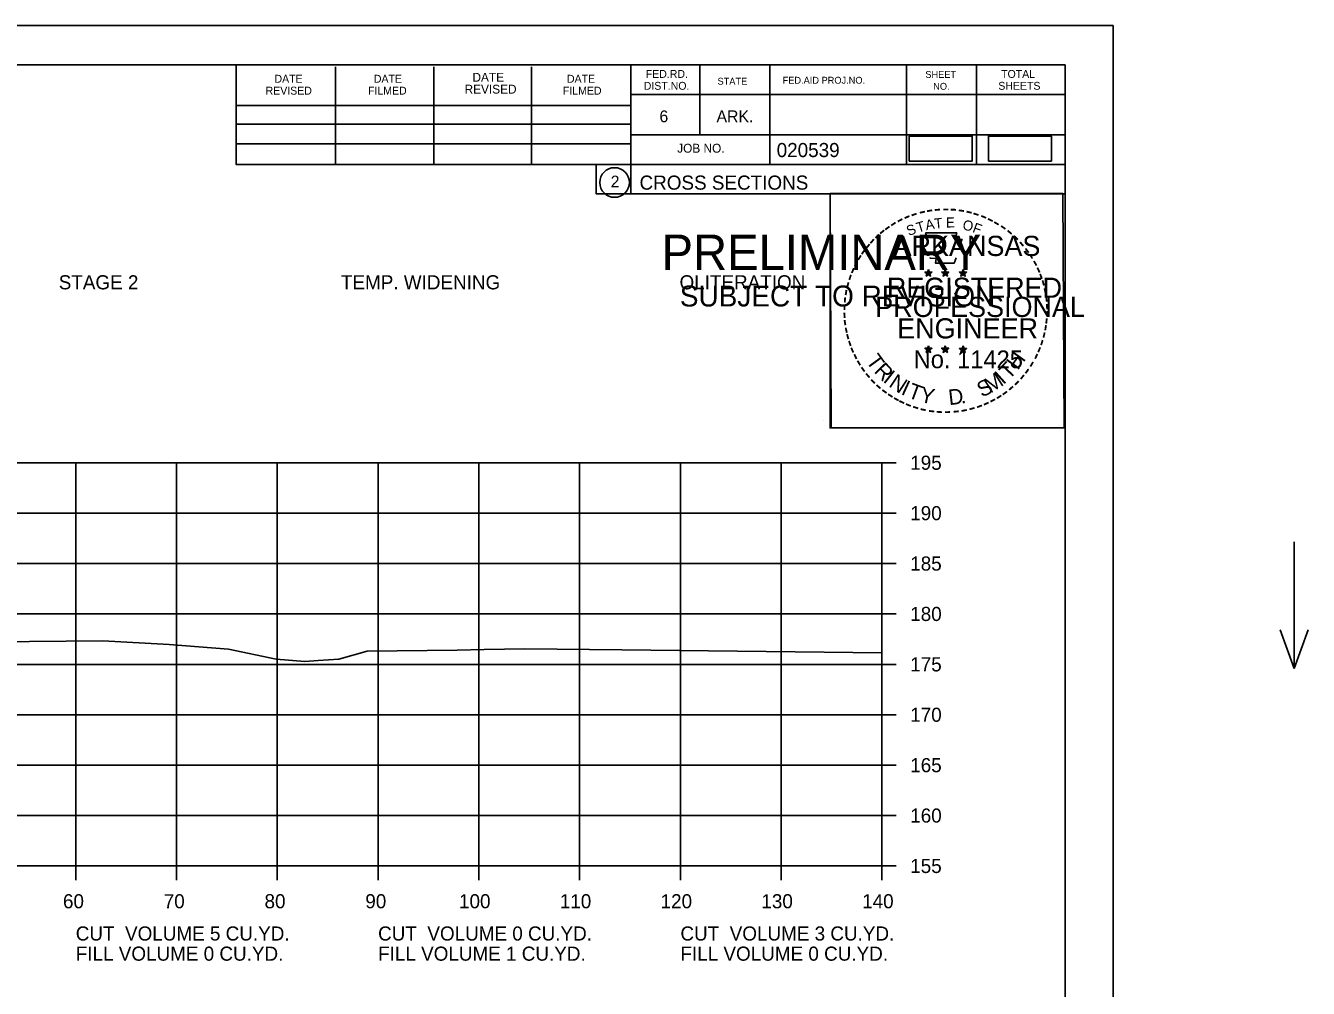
# Model space of a CAD drawing. Extents: x 915787 to 919910, y 133456 to 136717.
# Drawn here: x 916469 to 916596.3, y 133573.9 to 133669.4 of the extents above; entities that cross this region are included whole.
import ezdxf

# ---------------------------------------------------------------- set-up
doc = ezdxf.new("R2010")
doc.units = 0
for name, color, linetype in [('R_Axis', 7, 'Continuous'), ('R_Axis Annot', 7, 'Continuous'), ('R_Border', 7, 'Continuous'), ('R_Border Notes', 7, 'Continuous'), ('R_Border PE', 7, 'Continuous'), ('R_Border Prem', 7, 'Continuous'), ('R_Exist Surface', 7, 'Continuous'), ('R_Grid', 7, 'Continuous'), ('R_No Plot', 7, 'Continuous'), ('R_Water Annot', 7, 'Continuous'), ('R_Xsect Slope', 7, 'Continuous')]:
    doc.layers.add(name, color=color, linetype=linetype)

msp = doc.modelspace()

# ---------------------------------------------------------------- linework, layer by layer
at = {"layer": 'R_Axis'}
for p, q in [((916553.98, 133586.01), (916553.98, 133626.01)), ((916555.38, 133626.01), (916553.98, 133626.01)), ((916555.38, 133621.01), (916553.98, 133621.01)), ((916555.38, 133616.01), (916553.98, 133616.01)), ((916555.38, 133611.01), (916553.98, 133611.01)), ((916555.38, 133606.01), (916553.98, 133606.01)), ((916555.38, 133601.01), (916553.98, 133601.01)), ((916555.38, 133596.01), (916553.98, 133596.01)), ((916555.38, 133591.01), (916553.98, 133591.01)), ((916273.98, 133586.01), (916553.98, 133586.01)), ((916473.98, 133584.61), (916473.98, 133586.01)), ((916483.98, 133584.61), (916483.98, 133586.01)), ((916493.98, 133584.61), (916493.98, 133586.01)), ((916503.98, 133584.61), (916503.98, 133586.01)), ((916513.98, 133584.61), (916513.98, 133586.01)), ((916523.98, 133584.61), (916523.98, 133586.01)), ((916533.98, 133584.61), (916533.98, 133586.01)), ((916543.98, 133584.61), (916543.98, 133586.01)), ((916553.98, 133584.61), (916553.98, 133586.01)), ((916555.38, 133586.01), (916553.98, 133586.01))]:
    msp.add_line(p, q, dxfattribs=at)
at = {"layer": 'R_Border'}
for p, q in [((916255.98, 133665.47), (916572.16, 133665.47)), ((916489.9, 133655.59), (916489.9, 133665.47)), ((916499.76, 133655.59), (916499.76, 133665.27)), ((916509.52, 133655.59), (916509.52, 133665.27)), ((916519.2, 133655.59), (916519.2, 133665.27)), ((916529.06, 133665.47), (916529.06, 133652.67)), ((916535.9, 133665.47), (916535.9, 133658.53)), ((916542.84, 133665.47), (916542.84, 133655.59)), ((916556.42, 133665.47), (916556.42, 133655.59)), ((916563.36, 133665.47), (916563.36, 133655.59)), ((916572.16, 133460.01), (916572.16, 133665.47)), ((916489.9, 133661.45), (916529.06, 133661.45)), ((916572.16, 133662.53), (916529.06, 133662.53)), ((916572.16, 133662.55), (916572.16, 133662.55)), ((916489.9, 133659.59), (916529.06, 133659.59)), ((916489.9, 133655.59), (916489.9, 133657.65)), ((916489.9, 133657.65), (916529.06, 133657.65)), ((916572.16, 133658.53), (916529.06, 133658.53)), ((916532.02, 133658.53), (916572.16, 133658.53)), ((916572.16, 133655.59), (916489.9, 133655.59)), ((916529.06, 133652.67), (916572.16, 133652.67))]:
    msp.add_line(p, q, dxfattribs=at)
msp.add_circle((916527.44, 133653.81), 1.47, dxfattribs=at)
at = {"layer": 'R_Border PE'}
for p, q in [((916558.24, 133644.93), (916558.59, 133644.82)), ((916558.24, 133644.93), (916558.49, 133644.88)), ((916558.24, 133644.93), (916558.48, 133644.81)), ((916558.59, 133645.18), (916558.55, 133644.93)), ((916558.59, 133644.82), (916558.59, 133645.18)), ((916558.59, 133645.18), (916558.64, 133644.93)), ((916558.94, 133644.93), (916558.59, 133644.82)), ((916558.94, 133644.93), (916558.65, 133644.88)), ((916558.94, 133644.93), (916558.73, 133644.83)), ((916559.91, 133644.93), (916560.26, 133644.82)), ((916559.91, 133644.93), (916560.16, 133644.88)), ((916559.91, 133644.93), (916560.15, 133644.81)), ((916560.26, 133645.18), (916560.22, 133644.93)), ((916560.26, 133644.82), (916560.26, 133645.18)), ((916560.26, 133645.18), (916560.31, 133644.93)), ((916560.61, 133644.93), (916560.26, 133644.82)), ((916560.61, 133644.93), (916560.32, 133644.88)), ((916560.61, 133644.93), (916560.4, 133644.83)), ((916561.67, 133644.92), (916562.02, 133644.81)), ((916561.67, 133644.92), (916561.93, 133644.87)), ((916561.67, 133644.92), (916561.91, 133644.8)), ((916562.02, 133645.17), (916561.98, 133644.92)), ((916562.02, 133644.81), (916562.02, 133645.17)), ((916562.02, 133645.17), (916562.07, 133644.92)), ((916562.37, 133644.92), (916562.02, 133644.81)), ((916562.37, 133644.92), (916562.08, 133644.87)), ((916562.37, 133644.92), (916562.17, 133644.82)), ((916558.37, 133644.52), (916558.59, 133644.82)), ((916558.37, 133644.52), (916558.5, 133644.77)), ((916558.37, 133644.52), (916558.59, 133644.74)), ((916558.8, 133644.52), (916558.59, 133644.82)), ((916558.8, 133644.52), (916558.59, 133644.74)), ((916558.8, 133644.52), (916558.66, 133644.81)), ((916560.04, 133644.52), (916560.26, 133644.82)), ((916560.04, 133644.52), (916560.17, 133644.77)), ((916560.04, 133644.52), (916560.26, 133644.74)), ((916560.47, 133644.52), (916560.26, 133644.82)), ((916560.47, 133644.52), (916560.26, 133644.74)), ((916560.47, 133644.52), (916560.33, 133644.81)), ((916561.81, 133644.51), (916562.02, 133644.81)), ((916561.81, 133644.51), (916561.93, 133644.75)), ((916561.81, 133644.51), (916562.02, 133644.73)), ((916562.24, 133644.51), (916562.02, 133644.81)), ((916562.24, 133644.51), (916562.02, 133644.72)), ((916562.24, 133644.51), (916562.1, 133644.8)), ((916558.24, 133637.36), (916558.58, 133637.25)), ((916558.24, 133637.36), (916558.49, 133637.31)), ((916558.24, 133637.36), (916558.47, 133637.23)), ((916558.37, 133636.95), (916558.58, 133637.25)), ((916558.58, 133637.61), (916558.54, 133637.36)), ((916558.58, 133637.25), (916558.58, 133637.61)), ((916558.58, 133637.61), (916558.63, 133637.36)), ((916558.93, 133637.36), (916558.58, 133637.25)), ((916558.8, 133636.95), (916558.58, 133637.25)), ((916558.93, 133637.36), (916558.65, 133637.31)), ((916558.8, 133636.95), (916558.66, 133637.24)), ((916558.93, 133637.36), (916558.73, 133637.25)), ((916559.9, 133637.36), (916560.25, 133637.25)), ((916559.9, 133637.36), (916560.16, 133637.31)), ((916559.9, 133637.36), (916560.14, 133637.23)), ((916560.04, 133636.95), (916560.25, 133637.25)), ((916560.25, 133637.61), (916560.21, 133637.36)), ((916560.25, 133637.25), (916560.25, 133637.61)), ((916560.25, 133637.61), (916560.3, 133637.36)), ((916560.6, 133637.36), (916560.25, 133637.25)), ((916560.47, 133636.95), (916560.25, 133637.25)), ((916560.6, 133637.36), (916560.31, 133637.31)), ((916560.47, 133636.95), (916560.33, 133637.24)), ((916560.6, 133637.36), (916560.4, 133637.25)), ((916561.67, 133637.35), (916562.02, 133637.24)), ((916561.67, 133637.35), (916561.92, 133637.3)), ((916561.67, 133637.35), (916561.91, 133637.22)), ((916561.8, 133636.94), (916562.02, 133637.24)), ((916562.02, 133637.6), (916561.98, 133637.35)), ((916562.02, 133637.24), (916562.02, 133637.6)), ((916562.02, 133637.6), (916562.07, 133637.35)), ((916562.37, 133637.35), (916562.02, 133637.24)), ((916562.23, 133636.94), (916562.02, 133637.24)), ((916562.37, 133637.35), (916562.08, 133637.3)), ((916562.23, 133636.94), (916562.1, 133637.23)), ((916562.37, 133637.35), (916562.16, 133637.24)), ((916558.37, 133636.95), (916558.49, 133637.19)), ((916558.37, 133636.95), (916558.58, 133637.17)), ((916558.8, 133636.95), (916558.58, 133637.16)), ((916560.04, 133636.95), (916560.16, 133637.19)), ((916560.04, 133636.95), (916560.25, 133637.17)), ((916560.47, 133636.95), (916560.25, 133637.16)), ((916561.8, 133636.94), (916561.93, 133637.18)), ((916561.8, 133636.94), (916562.02, 133637.16)), ((916562.23, 133636.94), (916562.02, 133637.15))]:
    msp.add_line(p, q, dxfattribs=at)
for points in [[(916558.28, 133648.81), (916558.55, 133647.98)], [(916561.79, 133647.89), (916561.93, 133648.17), (916561.25, 133648.15), (916561.4, 133648.81), (916558.28, 133648.81)], [(916558.77, 133646.38), (916558.77, 133646.3), (916559.34, 133646.28), (916559.28, 133645.81), (916561.15, 133645.81), (916561.35, 133646.34)], [(916558.59, 133645.18), (916558.8, 133644.52), (916558.24, 133644.93), (916558.94, 133644.93), (916558.37, 133644.52), (916558.59, 133645.18)], [(916560.26, 133645.18), (916560.47, 133644.52), (916559.91, 133644.93), (916560.61, 133644.93), (916560.04, 133644.52), (916560.26, 133645.18)], [(916562.02, 133645.17), (916562.24, 133644.51), (916561.67, 133644.92), (916562.37, 133644.92), (916561.81, 133644.51), (916562.02, 133645.17)], [(916558.58, 133637.61), (916558.8, 133636.95), (916558.24, 133637.36), (916558.93, 133637.36), (916558.37, 133636.95), (916558.58, 133637.61)], [(916560.25, 133637.61), (916560.47, 133636.95), (916559.9, 133637.36), (916560.6, 133637.36), (916560.04, 133636.95), (916560.25, 133637.61)], [(916562.02, 133637.6), (916562.23, 133636.94), (916561.67, 133637.35), (916562.37, 133637.35), (916561.8, 133636.94), (916562.02, 133637.6)]]:
    msp.add_lwpolyline(points, dxfattribs=at)
for centre, radius in [((916558.59, 133644.82), 0.172), ((916558.59, 133644.82), 0.145), ((916558.59, 133644.82), 0.116), ((916558.59, 133644.82), 0.0991), ((916558.59, 133644.82), 0.0747), ((916558.59, 133644.82), 0.0495), ((916560.26, 133644.82), 0.172), ((916560.26, 133644.82), 0.145), ((916560.26, 133644.82), 0.116), ((916560.26, 133644.82), 0.0991), ((916560.26, 133644.82), 0.0747), ((916560.26, 133644.82), 0.0495), ((916562.02, 133644.81), 0.172), ((916562.02, 133644.81), 0.145), ((916562.02, 133644.81), 0.116), ((916562.02, 133644.81), 0.0991), ((916562.02, 133644.81), 0.0747), ((916562.02, 133644.81), 0.0495), ((916558.59, 133644.82), 0.0296), ((916560.26, 133644.82), 0.0296), ((916562.02, 133644.81), 0.0296), ((916558.58, 133637.25), 0.172), ((916558.58, 133637.25), 0.145), ((916558.58, 133637.25), 0.116), ((916558.58, 133637.25), 0.0991), ((916558.58, 133637.25), 0.0747), ((916558.58, 133637.25), 0.0495), ((916558.58, 133637.25), 0.0296), ((916560.25, 133637.25), 0.172), ((916560.25, 133637.25), 0.145), ((916560.25, 133637.25), 0.116), ((916560.25, 133637.25), 0.0991), ((916560.25, 133637.25), 0.0747), ((916560.25, 133637.25), 0.0495), ((916560.25, 133637.25), 0.0296), ((916562.02, 133637.24), 0.172), ((916562.02, 133637.24), 0.145), ((916562.02, 133637.24), 0.116), ((916562.02, 133637.24), 0.0991), ((916562.02, 133637.24), 0.0747), ((916562.02, 133637.24), 0.0495), ((916562.02, 133637.24), 0.0296)]:
    msp.add_circle(centre, radius, dxfattribs=at)
at = {"layer": 'R_Exist Surface'}
msp.add_lwpolyline([(916465.72, 133608.23), (916476.68, 133608.34), (916483.26, 133607.98), (916489.12, 133607.53), (916493.88, 133606.54), (916496.72, 133606.3), (916498.04, 133606.4), (916500.09, 133606.52), (916502.91, 133607.31), (916511.83, 133607.41), (916514.52, 133607.47), (916518.55, 133607.56), (916528.16, 133607.45), (916553.98, 133607.14)], dxfattribs=at)
at = {"layer": 'R_Grid'}
for p, q in [((916273.98, 133626.01), (916553.98, 133626.01)), ((916473.98, 133586.01), (916473.98, 133626.01)), ((916483.98, 133586.01), (916483.98, 133626.01)), ((916493.98, 133586.01), (916493.98, 133626.01)), ((916503.98, 133586.01), (916503.98, 133626.01)), ((916513.98, 133586.01), (916513.98, 133626.01)), ((916523.98, 133586.01), (916523.98, 133626.01)), ((916533.98, 133586.01), (916533.98, 133626.01)), ((916543.98, 133586.01), (916543.98, 133626.01)), ((916553.98, 133586.01), (916553.98, 133626.01)), ((916273.98, 133621.01), (916553.98, 133621.01)), ((916273.98, 133616.01), (916553.98, 133616.01)), ((916273.98, 133611.01), (916553.98, 133611.01)), ((916273.98, 133606.01), (916553.98, 133606.01)), ((916273.98, 133601.01), (916553.98, 133601.01)), ((916273.98, 133596.01), (916553.98, 133596.01)), ((916273.98, 133591.01), (916553.98, 133591.01)), ((916273.98, 133586.01), (916553.98, 133586.01))]:
    msp.add_line(p, q, dxfattribs=at)
at = {"layer": 'R_No Plot'}
for p, q in [((916243.57, 133669.37), (916576.91, 133669.37)), ((916548.19, 133630.22), (916548.19, 133630.22))]:
    msp.add_line(p, q, dxfattribs=at)
for points in [[(916243.57, 133669.37), (916576.91, 133669.37), (916576.91, 133456.03), (916243.57, 133456.03)], [(916489.9, 133665.47), (916489.9, 133655.59), (916525.63, 133655.59), (916525.63, 133652.67), (916548.83, 133652.67), (916548.83, 133629.46), (916572.16, 133629.46), (916572.16, 133460.01), (916255.98, 133460.01), (916255.98, 133665.47)], [(916548.83, 133652.71), (916571.92, 133652.71), (916572.04, 133629.46), (916548.94, 133629.46)]]:
    msp.add_lwpolyline(points, close=True, dxfattribs=at)
at = {"layer": 'R_Water Annot'}
for p, q in [((916594.88, 133618.16), (916594.88, 133605.59)), ((916594.88, 133605.59), (916593.48, 133609.44)), ((916594.88, 133605.59), (916596.28, 133609.44))]:
    msp.add_line(p, q, dxfattribs=at)
at = {"layer": 'R_Xsect Slope'}
for points in [[(916556.68, 133655.93), (916562.93, 133655.93), (916562.93, 133658.41), (916556.68, 133658.41)], [(916564.54, 133655.93), (916570.79, 133655.93), (916570.79, 133658.41), (916564.54, 133658.41)]]:
    msp.add_lwpolyline(points, close=True, dxfattribs=at)

# ---------------------------------------------------------------- texts
at = {"layer": 'R_Axis Annot'}
for s, p in [('195', (916556.78, 133625.31)), ('190', (916556.78, 133620.31)), ('185', (916556.78, 133615.31)), ('180', (916556.78, 133610.31)), ('175', (916556.78, 133605.31)), ('170', (916556.78, 133600.31)), ('165', (916556.78, 133595.31)), ('160', (916556.78, 133590.31)), ('155', (916556.78, 133585.31)), ('60', (916472.71, 133581.81)), ('70', (916482.71, 133581.81)), ('80', (916492.71, 133581.81)), ('90', (916502.71, 133581.81)), ('100', (916512.01, 133581.81)), ('110', (916522.01, 133581.81)), ('120', (916532.01, 133581.81)), ('130', (916542.01, 133581.81)), ('140', (916552.01, 133581.81))]:
    msp.add_text(s, height=1.4, dxfattribs=at).set_placement(p)
at = {"layer": 'R_Border'}
for s, height, p in [('DATE', 0.782, (916493.7, 133663.71)), ('DATE', 0.782, (916503.56, 133663.71)), ('DATE', 0.879, (916513.34, 133663.81)), ('DATE', 0.782, (916522.72, 133663.71)), ('FED.RD.', 0.782, (916530.54, 133664.19)), ('STATE', 0.684, (916537.66, 133663.51)), ('FED.AID PROJ.NO.', 0.684, (916544.12, 133663.61)), ('SHEET', 0.684, (916558.28, 133664.19)), ('TOTAL', 0.782, (916565.8, 133664.19)), ('REVISED', 0.782, (916492.82, 133662.53)), ('FILMED', 0.782, (916502.98, 133662.53)), ('REVISED', 0.879, (916512.56, 133662.63)), ('FILMED', 0.782, (916522.32, 133662.53)), ('DIST.NO.', 0.782, (916530.34, 133663.01)), ('NO.', 0.684, (916559.06, 133663.01)), ('SHEETS', 0.782, (916565.52, 133663.01)), ('6', 1.17, (916531.9, 133659.79)), ('ARK.', 1.172, (916537.56, 133659.79)), ('JOB NO.', 0.879, (916533.66, 133656.77)), ('020539', 1.4, (916543.53, 133656.33)), ('2', 1.17, (916527.06, 133653.32)), ('CROSS SECTIONS', 1.4, (916529.92, 133653.1))]:
    msp.add_text(s, height=height, rotation=360, dxfattribs=at).set_placement(p)
at = {"layer": 'R_Border Notes'}
for s, p in [('STAGE 2', (916472.29, 133643.21)), ('TEMP. WIDENING', (916500.29, 133643.21)), ('OLITERATION', (916533.89, 133643.21)), ('CUT  VOLUME 5 CU.YD.', (916473.98, 133578.61)), ('CUT  VOLUME 0 CU.YD.', (916503.98, 133578.61)), ('CUT  VOLUME 3 CU.YD.', (916533.98, 133578.61)), ('FILL VOLUME 0 CU.YD.', (916473.98, 133576.61)), ('FILL VOLUME 1 CU.YD.', (916503.98, 133576.61)), ('FILL VOLUME 0 CU.YD.', (916533.98, 133576.61))]:
    msp.add_text(s, height=1.4, dxfattribs=at).set_placement(p)
at = {"layer": 'R_Border PE'}
for s, height, rotation, p in [('-', 1.6, 0.1862, (916559.96, 133650.52)), ('-', 1.6, 28.7918, (916555.76, 133649.35)), ('-', 1.6, 24.3072, (916556.39, 133649.67)), ('-', 1.6, 19.1761, (916557.03, 133649.93)), ('T', 1, 16.4036, (916557.55, 133648.82)), ('-', 1.6, 13.6301, (916557.78, 133650.18)), ('A', 1, 11.2132, (916558.38, 133649.07)), ('-', 1.6, 10.2193, (916558.46, 133650.34)), ('T', 1, 6.0228, (916559.22, 133649.23)), ('-', 1.6, 5.8968, (916559.19, 133650.45)), ('E', 1, 0.8323, (916560.33, 133649.34)), ('-', 1.6, 357.743, (916560.68, 133650.51)), ('-', 1.6, 352.1617, (916561.42, 133650.45)), ('O', 1, 350.4515, (916561.93, 133649.13)), ('-', 1.6, 347.2049, (916562.14, 133650.34)), ('-', 1.6, 342.3362, (916562.78, 133650.18)), ('-', 1.6, 337.8551, (916563.51, 133649.96)), ('-', 1.6, 334.1211, (916564.14, 133649.69)), ('-', 1.6, 329.6409, (916564.72, 133649.4)), ('-', 1.6, 42.9622, (916553.68, 133647.79)), ('-', 1.6, 38.9507, (916554.11, 133648.21)), ('-', 1.6, 36.2317, (916554.59, 133648.58)), ('-', 1.6, 34.0636, (916555.16, 133648.98)), ('S', 1, 21.594, (916556.64, 133648.49)), ('F', 1, 340.0707, (916562.89, 133648.91)), ('-', 1.6, 325.8627, (916565.37, 133649.04)), ('-', 1.6, 320.5297, (916565.98, 133648.62)), ('-', 1.6, 50.6142, (916552.83, 133646.82)), ('-', 1.6, 48.423, (916553.23, 133647.31)), ('ARKANSAS', 2, 360, (916555.13, 133646.52)), ('-', 1.6, 315.5786, (916566.58, 133648.13)), ('-', 1.6, 309.8797, (916567.14, 133647.58)), ('-', 1.6, 58.0706, (916552.09, 133645.73)), ('-', 1.6, 54.2325, (916552.41, 133646.26)), ('-', 1.6, 306.6522, (916567.67, 133646.98)), ('-', 1.4, 303.6753, (916568.16, 133646.41)), ('-', 1.6, 67.7743, (916551.52, 133644.51)), ('-', 1.6, 62.8713, (916551.78, 133645.12)), ('-', 1.6, 299.6684, (916568.47, 133645.8)), ('-', 1.6, 294.6628, (916568.8, 133645.19)), ('-', 1.6, 75.461, (916551.1, 133643.16)), ('-', 1.6, 72.3945, (916551.3, 133643.88)), ('REGISTERED', 2, 360, (916554.46, 133642.37)), ('DWB', 0.01, 360, (916558.58, 133644.81)), ('DWB', 0.01, 360, (916560.25, 133644.81)), ('DWB', 0.01, 360, (916562.01, 133644.8)), ('-', 1.6, 290.5728, (916569.06, 133644.61)), ('-', 1.6, 285.1233, (916569.29, 133644.03)), ('-', 1.6, 85.1863, (916550.89, 133641.76)), ('-', 1.6, 81.2013, (916550.97, 133642.45)), ('PROFESSIONAL', 2, 360, (916553.31, 133640.47)), ('-', 1.6, 280.5493, (916569.49, 133643.29)), ('-', 1.6, 276.5962, (916569.65, 133642.52)), ('-', 1.6, 89.0622, (916550.87, 133641.06)), ('-', 1.6, 274.3301, (916569.71, 133641.8)), ('-', 1.6, 269.9407, (916569.75, 133641.17)), ('-', 1.6, 94.1959, (916550.9, 133640.33)), ('-', 1.6, 98.9479, (916550.97, 133639.66)), ('ENGINEER', 2, 360, (916555.49, 133638.34)), ('-', 1.6, 263.5172, (916569.73, 133640.5)), ('-', 1.6, 101.7149, (916551.11, 133638.93)), ('-', 1.6, 105.4578, (916551.27, 133638.34)), ('-', 1.6, 255.7626, (916569.55, 133639.17)), ('-', 1.6, 260.9953, (916569.66, 133639.85)), ('-', 1.6, 109.0874, (916551.49, 133637.71)), ('-', 1.6, 114.0643, (916551.74, 133637.11)), ('DWB', 0.01, 360, (916558.57, 133637.24)), ('DWB', 0.01, 360, (916560.24, 133637.24)), ('DWB', 0.01, 360, (916562.01, 133637.23)), ('-', 1.6, 247.8887, (916569.14, 133637.78)), ('-', 1.6, 252.8681, (916569.36, 133638.45)), ('-', 1.6, 115.7289, (916552.05, 133636.49)), ('-', 1.6, 120.4471, (916552.4, 133635.91)), ('T', 1.54, 306.0406, (916552.34, 133636.08)), ('R', 1.54, 314.005, (916553.11, 133635.04)), ('No. 11425', 1.757, 360, (916557.12, 133635.39)), ('T', 1.54, 46.6444, (916566.58, 133634.18)), ('H', 1.54, 54.6088, (916567.46, 133635.12)), ('-', 1.6, 239.0712, (916568.49, 133636.4)), ('-', 1.6, 244.6197, (916568.88, 133637.15)), ('-', 1.6, 125.8934, (916552.81, 133635.34)), ('-', 1.6, 130.7181, (916553.27, 133634.79)), ('I', 1.54, 321.9694, (916554.01, 133634.1)), ('N', 1.54, 326.5002, (916554.57, 133633.63)), ('M', 1.54, 32.6563, (916564.73, 133632.85)), ('I', 1.54, 42.1136, (916566.01, 133633.7)), ('-', 1.6, 231.2538, (916567.65, 133635.18)), ('-', 1.6, 233.8452, (916568.08, 133635.74)), ('-', 1.6, 134.2238, (916553.78, 133634.25)), ('-', 1.6, 138.9338, (916554.31, 133633.78)), ('I', 1.54, 335.3603, (916555.78, 133632.85)), ('T', 1.54, 339.8912, (916556.44, 133632.52)), ('Y', 1.54, 347.8556, (916557.66, 133632.07)), ('S', 1.54, 26.9312, (916563.89, 133632.45)), ('-', 1.6, 221.0851, (916566.65, 133634.11)), ('-', 1.6, 225.7653, (916567.17, 133634.61)), ('-', 1.6, 144.6463, (916554.87, 133633.38)), ('-', 1.6, 148.0898, (916555.43, 133633.01)), ('-', 1.6, 151.5704, (916556.01, 133632.68)), ('-', 1.6, 154.6002, (916556.53, 133632.43)), ('D', 1.54, 6.3969, (916560.65, 133631.72)), ('.', 1.54, 13.7642, (916561.84, 133631.84)), ('-', 1.6, 207.3568, (916565.01, 133632.9)), ('-', 1.6, 212.2491, (916565.57, 133633.25)), ('-', 1.6, 215.7363, (916566.1, 133633.63)), ('-', 1.6, 158.5612, (916557.15, 133632.18)), ('-', 1.6, 162.7983, (916557.84, 133631.97)), ('-', 1.6, 167.5555, (916558.55, 133631.8)), ('-', 1.6, 173.1155, (916559.33, 133631.69)), ('-', 1.6, 176.5183, (916560.07, 133631.64)), ('-', 1.6, 181.5918, (916560.82, 133631.66)), ('-', 1.6, 185.8167, (916561.63, 133631.74)), ('-', 1.6, 191.2858, (916562.36, 133631.87)), ('-', 1.6, 195.4743, (916563.09, 133632.07)), ('-', 1.6, 200.7184, (916563.77, 133632.31)), ('-', 1.6, 204.2516, (916564.39, 133632.58))]:
    msp.add_text(s, height=height, rotation=rotation, dxfattribs=at).set_placement(p)
at = {"layer": 'R_Border Prem'}
for s, height, p in [('PRELIMINARY', 3.5, (916532.11, 133645.14)), ('DWB', 0.01, (916532.85, 133646.99)), ('SUBJECT TO REVISION', 2.0751, (916533.92, 133641.51))]:
    msp.add_text(s, height=height, rotation=360, dxfattribs=at).set_placement(p)

doc.saveas('drawing.dxf')
